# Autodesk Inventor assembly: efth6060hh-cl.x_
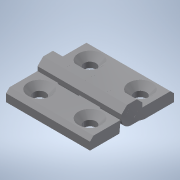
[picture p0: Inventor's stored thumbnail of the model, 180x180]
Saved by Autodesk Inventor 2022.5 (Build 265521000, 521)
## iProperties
Part Number: efth6060hh-cl.x_
Material: 一般
Document SubType Name: Assembly
Designer: ImaoCorp
Sending System: SOLIDWORKS 2017-2017317
MC: AMD64
MC_MODEL: Intel64 Family 6 Model 60 Stepping 3, GenuineIntel
OS: Windows_NT
FRU: Parasolid Version 29.0, build 201,  4-17-2017
FORMAT: text
GUISE: transmit
KEY: efth6060hh-cl
FILE: efth6060hh-cl.x_t
DATE: Mon May 13 14:22:06 2019
Author: ImaoCorp
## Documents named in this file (4)
- X:\14_SW2022-Inv2022\00_全2023-1023新製品(TCC)まで\e\efth6060hh-cl\EFTH6060HH-CL.iam
- X:\14_SW2022-Inv2022\00_全2023-1023新製品(TCC)まで\e\efth6060hh-cl\efth6060hh-cl_01.ipt
- X:\14_SW2022-Inv2022\00_全2023-1023新製品(TCC)まで\e\efth6060hh-cl\efth6060hh-cl_02.ipt
- X:\14_SW2022-Inv2022\00_全2023-1023新製品(TCC)まで\e\efth6060hh-cl\efth6060hh-cl_03.ipt
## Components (3 placed, 3 different names)
1. efth6060hh-cl_01
2. efth6060hh-cl_02
3. efth6060hh-cl_03
